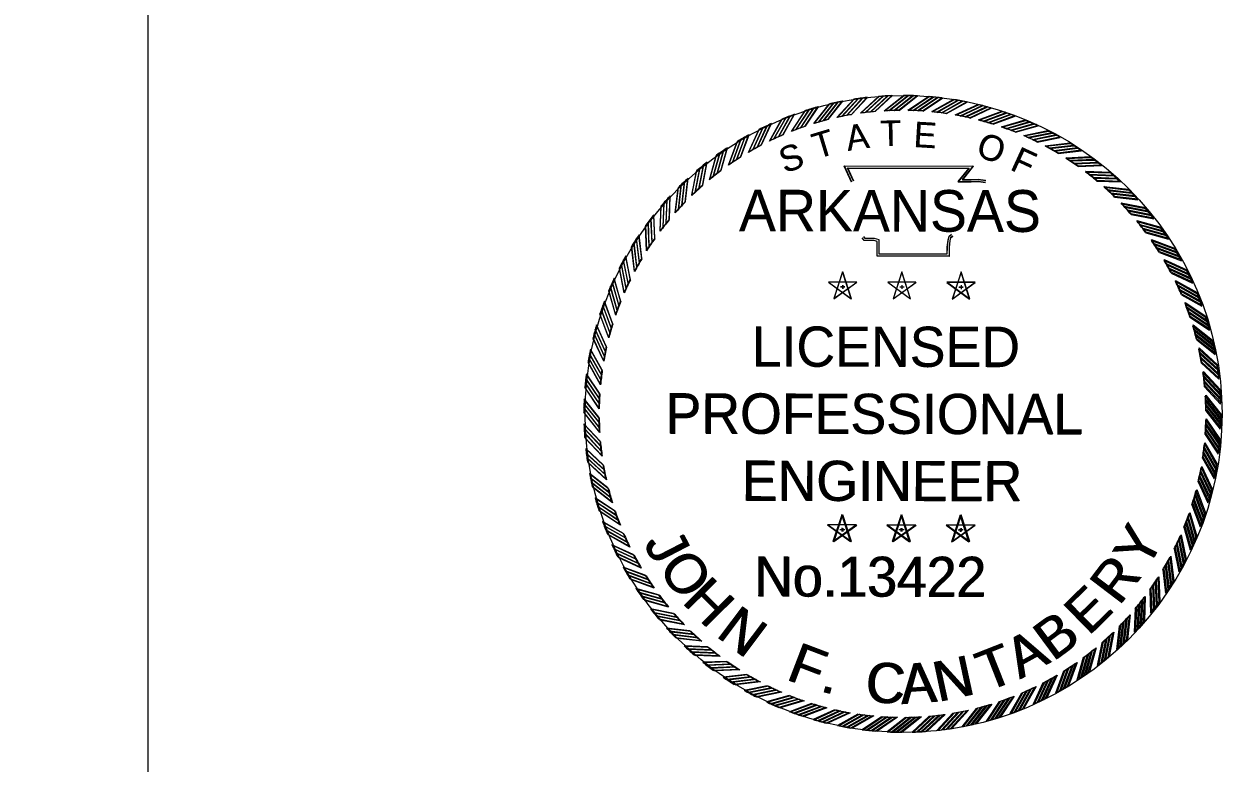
# Model space of a CAD drawing. Extents: x 0 to 19, y -0.6 to 11.2.
# Drawn here: x 16.766 to 19.023, y 7.658 to 9.05 of the extents above; entities that cross this region are included whole.
import ezdxf

# ---------------------------------------------------------------- set-up
doc = ezdxf.new("R2010")
doc.units = 0
for name, color, linetype in [('Default', 7, 'Continuous'), ('G-ANNO-SYMB', 7, 'Continuous'), ('G-ANNO-TEXT', 7, 'Continuous'), ('G-Border-Paper', 7, 'Continuous'), ('G-No Plot-Stamp-1', 7, 'Continuous')]:
    doc.layers.add(name, color=color, linetype=linetype)

# ---------------------------------------------------------------- blocks, each defined once
blk = doc.blocks.new('STAR')
at = {"layer": 'Default'}
for p, q in [((-0.0001, 0.0615), (-0.0366, -0.0504)), ((0.0362, -0.0503), (0, 0.0617)), ((0.0587, 0.0188), (-0.059, 0.0189)), ((-0.0589, 0.0188), (0.0363, -0.0505)), ((-0.0365, -0.0503), (0.0589, 0.0188)), ((-0.0085, 0), (0.009, 0)), ((0, 0.0063), (0, -0.0085))]:
    blk.add_line(p, q, dxfattribs=at)
blk = doc.blocks.new('RP')
at = {"layer": 'Default'}
for p, q in [((-0.0781, 1.2656), (0.003, 1.33)), ((-0.058, 1.2667), (0.0216, 1.3299)), ((-0.0375, 1.2674), (0.0405, 1.3294)), ((-0.0176, 1.2679), (0.059, 1.3287))]:
    blk.add_line(p, q, dxfattribs=at)
for radius, start, end in [(1.33, 87.4562, 89.8699), (1.268, 90.7933, 93.5307)]:
    blk.add_arc((0, 0), radius, start, end, dxfattribs=at)

msp = doc.modelspace()

# ---------------------------------------------------------------- linework, layer by layer
at = {"layer": 'G-ANNO-SYMB'}
for points in [[(18.3256, 8.7521), (18.3116, 8.7824), (18.5542, 8.7826), (18.5339, 8.7571), (18.5504, 8.7573), (18.5641, 8.7575), (18.5779, 8.756)], [(18.3261, 8.7522), (18.3121, 8.7827), (18.5547, 8.782), (18.5344, 8.7566), (18.5509, 8.7567), (18.5646, 8.7569), (18.5784, 8.7553)], [(18.3291, 8.7537), (18.3176, 8.7786), (18.5462, 8.7787), (18.5258, 8.7532), (18.5504, 8.7535), (18.564, 8.7537), (18.5775, 8.7522)], [(18.3295, 8.7538), (18.3181, 8.7788), (18.5468, 8.7781), (18.5263, 8.7526), (18.5509, 8.7529), (18.5644, 8.753), (18.5779, 8.7515)], [(18.5159, 8.6504), (18.5118, 8.647), (18.5104, 8.642), (18.509, 8.6294), (18.509, 8.6127), (18.3736, 8.6127), (18.3736, 8.6353), (18.3736, 8.6403), (18.3681, 8.642), (18.3489, 8.642), (18.3454, 8.6472)], [(18.5161, 8.6499), (18.5119, 8.6466), (18.5105, 8.6415), (18.5091, 8.629), (18.509, 8.6122), (18.3736, 8.6127), (18.3737, 8.6353), (18.3737, 8.6403), (18.3682, 8.642), (18.349, 8.6421), (18.3456, 8.6473)], [(18.5135, 8.6534), (18.5084, 8.6492), (18.5066, 8.6427), (18.5052, 8.6296), (18.5052, 8.6165), (18.3775, 8.6165), (18.3775, 8.6353), (18.3775, 8.6432), (18.3687, 8.6459), (18.3509, 8.6459), (18.3487, 8.6493)], [(18.5136, 8.6529), (18.5085, 8.6488), (18.5067, 8.6423), (18.5053, 8.6292), (18.5052, 8.6161), (18.3775, 8.6165), (18.3775, 8.6353), (18.3776, 8.6432), (18.3688, 8.6459), (18.3511, 8.6459), (18.3488, 8.6494)]]:
    msp.add_lwpolyline(points, dxfattribs=at)
at = {"layer": 'G-Border-Paper'}
msp.add_lwpolyline([(17, 11), (0, 11), (0, 0), (17, 0)], close=True, dxfattribs=at)
at = {"layer": 'G-No Plot-Stamp-1'}
msp.add_circle((18.4233, 8.3154), 0.6, dxfattribs=at)

# ---------------------------------------------------------------- block references
at = {"layer": 'G-ANNO-SYMB'}
for name, p, xscale, yscale, rotation in [('RP', (18.4219, 8.3156), 0.45103579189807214, 0.4510357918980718, 4.500000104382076), ('RP', (18.4209, 8.3154), 0.451035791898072, 0.45103579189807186, 4.304199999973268), ('RP', (18.4219, 8.3156), 0.451035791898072, 0.45103579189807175, 1.0438208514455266e-07), ('RP', (18.4209, 8.3154), 0.45103579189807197, 0.4510357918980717, -0.19580000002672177), ('RP', (18.4219, 8.3156), 0.451035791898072, 0.4510357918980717, -4.499999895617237), ('RP', (18.4209, 8.3154), 0.451035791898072, 0.45103579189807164, -4.695800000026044), ('RP', (18.4219, 8.3156), 0.4510357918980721, 0.4510357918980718, 18.00000010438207), ('RP', (18.4209, 8.3154), 0.45103579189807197, 0.4510357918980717, 17.804199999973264), ('RP', (18.4219, 8.3156), 0.45103579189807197, 0.45103579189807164, 13.500000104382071), ('RP', (18.4209, 8.3154), 0.45103579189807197, 0.45103579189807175, 13.304199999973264), ('RP', (18.4219, 8.3156), 0.45103579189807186, 0.4510357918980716, 9.000000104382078), ('RP', (18.4209, 8.3154), 0.4510357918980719, 0.45103579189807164, 8.804199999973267), ('RP', (18.4219, 8.3156), 0.4510357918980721, 0.45103579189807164, -8.999999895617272), ('RP', (18.4209, 8.3154), 0.45103579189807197, 0.45103579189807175, -9.195800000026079), ('RP', (18.4219, 8.3156), 0.45103579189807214, 0.45103579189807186, -13.499999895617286), ('RP', (18.4209, 8.3154), 0.4510357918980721, 0.4510357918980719, -13.695800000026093), ('RP', (18.4219, 8.3156), 0.45103579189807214, 0.4510357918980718, -17.99999989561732), ('RP', (18.4209, 8.3154), 0.4510357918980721, 0.4510357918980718, -18.19580000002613), ('RP', (18.4219, 8.3156), 0.45103579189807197, 0.45103579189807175, 22.500000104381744), ('RP', (18.4209, 8.3154), 0.451035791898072, 0.4510357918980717, 22.304199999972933), ('RP', (18.4219, 8.3156), 0.451035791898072, 0.45103579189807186, -22.499999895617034), ('RP', (18.4209, 8.3154), 0.45103579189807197, 0.4510357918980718, -22.695800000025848), ('RP', (18.4219, 8.3156), 0.451035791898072, 0.45103579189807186, 27.000000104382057), ('RP', (18.4209, 8.3154), 0.45103579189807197, 0.4510357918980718, 26.80419999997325), ('RP', (18.4219, 8.3156), 0.4510357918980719, 0.45103579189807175, -26.99999989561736), ('RP', (18.4209, 8.3154), 0.45103579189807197, 0.45103579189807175, -27.19580000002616), ('RP', (18.4219, 8.3156), 0.45103579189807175, 0.45103579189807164, 31.500000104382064), ('RP', (18.4209, 8.3154), 0.4510357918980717, 0.4510357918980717, 31.30419999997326), ('RP', (18.4219, 8.3156), 0.45103579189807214, 0.45103579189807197, -31.49999989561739), ('RP', (18.4209, 8.3154), 0.4510357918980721, 0.45103579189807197, -31.695800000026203), ('RP', (18.4219, 8.3156), 0.4510357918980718, 0.45103579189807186, 36.00000010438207), ('RP', (18.4209, 8.3154), 0.4510357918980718, 0.45103579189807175, 35.80419999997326), ('RP', (18.4219, 8.3156), 0.4510357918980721, 0.4510357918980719, -35.999999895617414), ('RP', (18.4209, 8.3154), 0.451035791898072, 0.45103579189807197, -36.195800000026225), ('RP', (18.4219, 8.3156), 0.4510357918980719, 0.45103579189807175, 40.50000010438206), ('RP', (18.4209, 8.3154), 0.45103579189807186, 0.45103579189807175, 40.30419999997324), ('RP', (18.4219, 8.3156), 0.45103579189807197, 0.451035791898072, -40.49999989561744), ('RP', (18.4209, 8.3154), 0.45103579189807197, 0.45103579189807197, -40.69580000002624), ('RP', (18.4219, 8.3156), 0.45103579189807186, 0.451035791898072, 45.00000010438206), ('RP', (18.4209, 8.3154), 0.45103579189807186, 0.4510357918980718, 44.80419999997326), ('RP', (18.4219, 8.3156), 0.45103579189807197, 0.45103579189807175, -44.99999989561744), ('RP', (18.4209, 8.3154), 0.4510357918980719, 0.45103579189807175, -45.19580000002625), ('RP', (18.4219, 8.3156), 0.45103579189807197, 0.451035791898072, 49.500000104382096), ('RP', (18.4209, 8.3154), 0.451035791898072, 0.451035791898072, 49.304199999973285), ('RP', (18.4219, 8.3156), 0.4510357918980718, 0.4510357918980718, -49.499999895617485), ('RP', (18.4209, 8.3154), 0.4510357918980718, 0.45103579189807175, -49.695800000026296), ('RP', (18.4219, 8.3156), 0.45103579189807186, 0.4510357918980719, 54.00000010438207), ('RP', (18.4209, 8.3154), 0.4510357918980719, 0.4510357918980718, 53.804199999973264), ('RP', (18.4219, 8.3156), 0.45103579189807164, 0.45103579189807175, -53.999999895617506), ('RP', (18.4209, 8.3154), 0.45103579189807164, 0.4510357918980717, -54.1958000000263), ('RP', (18.4209, 8.3154), 0.45103579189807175, 0.4510357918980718, 58.304199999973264), ('RP', (18.4219, 8.3156), 0.4510357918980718, 0.4510357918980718, 58.50000010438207), ('RP', (18.4219, 8.3156), 0.4510357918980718, 0.4510357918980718, -58.49999989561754), ('RP', (18.4209, 8.3154), 0.45103579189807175, 0.4510357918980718, -58.69580000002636), ('RP', (18.4209, 8.3154), 0.4510357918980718, 0.4510357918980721, 62.804199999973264), ('RP', (18.4219, 8.3156), 0.4510357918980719, 0.451035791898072, 63.000000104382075), ('RP', (18.4219, 8.3156), 0.45103579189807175, 0.45103579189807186, -62.999999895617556), ('RP', (18.4209, 8.3154), 0.4510357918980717, 0.4510357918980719, -63.19580000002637), ('STAR', (18.3085, 8.5553), 0.45103579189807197, 0.4510357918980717, -0.19580000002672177), ('STAR', (18.3087, 8.5551), 0.451035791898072, 0.45103579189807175, 1.0438208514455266e-07), ('STAR', (18.4201, 8.5549), 0.45103579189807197, 0.4510357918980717, -0.19580000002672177), ('STAR', (18.4203, 8.5551), 0.451035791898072, 0.45103579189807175, 1.0438208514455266e-07), ('STAR', (18.5316, 8.5545), 0.45103579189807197, 0.4510357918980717, -0.19580000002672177), ('STAR', (18.5318, 8.5551), 0.451035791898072, 0.45103579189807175, 1.0438208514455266e-07), ('RP', (18.4219, 8.3156), 0.45103579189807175, 0.45103579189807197, -67.49999989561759), ('RP', (18.4209, 8.3154), 0.4510357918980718, 0.4510357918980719, 67.30419999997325), ('RP', (18.4219, 8.3156), 0.4510357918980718, 0.45103579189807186, 67.50000010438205), ('RP', (18.4209, 8.3154), 0.4510357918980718, 0.45103579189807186, -67.69580000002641), ('RP', (18.4209, 8.3154), 0.45103579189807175, 0.45103579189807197, -72.19580000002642), ('RP', (18.4219, 8.3156), 0.4510357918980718, 0.45103579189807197, -71.99999989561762), ('RP', (18.4209, 8.3154), 0.45103579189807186, 0.451035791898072, 71.80419999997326), ('RP', (18.4219, 8.3156), 0.4510357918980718, 0.4510357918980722, 72.00000010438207), ('RP', (18.4209, 8.3154), 0.4510357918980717, 0.4510357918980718, -76.69580000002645), ('RP', (18.4219, 8.3156), 0.45103579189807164, 0.4510357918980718, -76.49999989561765), ('RP', (18.4209, 8.3154), 0.4510357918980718, 0.4510357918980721, 76.30419999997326), ('RP', (18.4219, 8.3156), 0.4510357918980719, 0.451035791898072, 76.50000010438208), ('RP', (18.4209, 8.3154), 0.45103579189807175, 0.45103579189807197, -81.19580000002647), ('RP', (18.4219, 8.3156), 0.4510357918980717, 0.4510357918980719, -80.99999989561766), ('RP', (18.4209, 8.3154), 0.4510357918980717, 0.45103579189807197, 80.80419999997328), ('RP', (18.4219, 8.3156), 0.4510357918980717, 0.451035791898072, 81.0000001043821), ('RP', (18.4219, 8.3156), 0.45103579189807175, 0.4510357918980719, -85.49999989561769), ('RP', (18.4209, 8.3154), 0.4510357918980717, 0.4510357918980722, 85.30419999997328), ('RP', (18.4219, 8.3156), 0.45103579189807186, 0.451035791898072, 85.50000010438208), ('RP', (18.4209, 8.3154), 0.4510357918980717, 0.4510357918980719, -85.69580000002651), ('RP', (18.4209, 8.3154), 0.45103579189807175, 0.451035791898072, 89.80419999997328), ('RP', (18.4219, 8.3156), 0.45103579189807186, 0.45103579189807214, 90.0000001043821), ('RP', (18.4209, 8.3154), 0.4510357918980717, 0.451035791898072, -90.19580000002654), ('RP', (18.4219, 8.3156), 0.45103579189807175, 0.45103579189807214, -89.99999989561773), ('RP', (18.4209, 8.3154), 0.45103579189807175, 0.4510357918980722, 94.30419999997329), ('RP', (18.4219, 8.3156), 0.45103579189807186, 0.4510357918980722, 94.5000001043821), ('RP', (18.4209, 8.3154), 0.4510357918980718, 0.45103579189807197, -94.69580000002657), ('RP', (18.4219, 8.3156), 0.45103579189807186, 0.4510357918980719, -94.49999989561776), ('RP', (18.4219, 8.3156), 0.4510357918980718, 0.45103579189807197, -98.99999989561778), ('RP', (18.4209, 8.3154), 0.45103579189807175, 0.45103579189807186, 98.8041999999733), ('RP', (18.4219, 8.3156), 0.4510357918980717, 0.4510357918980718, 99.0000001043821), ('RP', (18.4209, 8.3154), 0.45103579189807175, 0.45103579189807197, -99.19580000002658), ('RP', (18.4219, 8.3156), 0.4510357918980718, 0.45103579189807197, -103.49999989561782), ('RP', (18.4209, 8.3154), 0.4510357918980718, 0.4510357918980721, 103.30419999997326), ('RP', (18.4219, 8.3156), 0.45103579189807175, 0.451035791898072, 103.50000010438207), ('RP', (18.4209, 8.3154), 0.4510357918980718, 0.45103579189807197, -103.69580000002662), ('RP', (18.4209, 8.3154), 0.45103579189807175, 0.45103579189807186, -108.19580000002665), ('RP', (18.4219, 8.3156), 0.4510357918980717, 0.451035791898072, -107.99999989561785), ('RP', (18.4209, 8.3154), 0.45103579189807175, 0.4510357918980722, 107.80419999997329), ('RP', (18.4219, 8.3156), 0.45103579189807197, 0.45103579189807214, 108.0000001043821), ('STAR', (18.3069, 8.0978), 0.45103579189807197, 0.4510357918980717, -0.19580000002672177), ('STAR', (18.3087, 8.0976), 0.451035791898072, 0.45103579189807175, 1.0438208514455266e-07), ('STAR', (18.4185, 8.0974), 0.45103579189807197, 0.4510357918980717, -0.19580000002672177), ('STAR', (18.4203, 8.0976), 0.451035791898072, 0.45103579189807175, 1.0438208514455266e-07), ('STAR', (18.5318, 8.0976), 0.451035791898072, 0.45103579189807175, 1.0438208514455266e-07), ('RP', (18.4209, 8.3154), 0.4510357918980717, 0.4510357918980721, -112.69580000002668), ('RP', (18.4219, 8.3156), 0.45103579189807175, 0.45103579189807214, -112.49999989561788), ('RP', (18.4209, 8.3154), 0.45103579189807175, 0.45103579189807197, 112.30419999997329), ('RP', (18.4219, 8.3156), 0.4510357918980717, 0.45103579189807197, 112.5000001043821), ('STAR', (18.5301, 8.097), 0.45103579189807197, 0.4510357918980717, -0.19580000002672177), ('RP', (18.4209, 8.3154), 0.4510357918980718, 0.45103579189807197, 116.80419999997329), ('RP', (18.4209, 8.3154), 0.4510357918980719, 0.451035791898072, -117.19580000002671), ('RP', (18.4219, 8.3156), 0.451035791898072, 0.4510357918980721, -116.9999998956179), ('RP', (18.4219, 8.3156), 0.4510357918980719, 0.45103579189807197, 117.0000001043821), ('RP', (18.4209, 8.3154), 0.45103579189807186, 0.45103579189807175, 121.30419999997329), ('RP', (18.4219, 8.3156), 0.45103579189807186, 0.45103579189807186, 121.5000001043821), ('RP', (18.4209, 8.3154), 0.4510357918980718, 0.4510357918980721, -121.69580000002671), ('RP', (18.4219, 8.3156), 0.4510357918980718, 0.4510357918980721, -121.4999998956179), ('RP', (18.4209, 8.3154), 0.45103579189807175, 0.45103579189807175, 125.80419999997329), ('RP', (18.4219, 8.3156), 0.4510357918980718, 0.4510357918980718, 126.00000010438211), ('RP', (18.4209, 8.3154), 0.4510357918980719, 0.45103579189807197, -126.19580000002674), ('RP', (18.4219, 8.3156), 0.45103579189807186, 0.45103579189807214, -125.99999989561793), ('RP', (18.4209, 8.3154), 0.45103579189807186, 0.4510357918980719, -130.6958000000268), ('RP', (18.4219, 8.3156), 0.45103579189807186, 0.4510357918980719, -130.49999989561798), ('RP', (18.4209, 8.3154), 0.4510357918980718, 0.4510357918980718, 130.3041999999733), ('RP', (18.4219, 8.3156), 0.4510357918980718, 0.45103579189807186, 130.50000010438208), ('RP', (18.4209, 8.3154), 0.45103579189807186, 0.4510357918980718, 134.80419999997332), ('RP', (18.4219, 8.3156), 0.45103579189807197, 0.4510357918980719, 135.00000010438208), ('RP', (18.4209, 8.3154), 0.45103579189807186, 0.4510357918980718, -135.19580000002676), ('RP', (18.4219, 8.3156), 0.45103579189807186, 0.451035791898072, -134.99999989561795), ('RP', (18.4209, 8.3154), 0.4510357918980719, 0.45103579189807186, 139.30419999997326), ('RP', (18.4209, 8.3154), 0.4510357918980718, 0.45103579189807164, -139.69580000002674), ('RP', (18.4219, 8.3156), 0.4510357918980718, 0.45103579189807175, -139.49999989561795), ('RP', (18.4219, 8.3156), 0.4510357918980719, 0.45103579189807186, 139.50000010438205), ('RP', (18.4209, 8.3154), 0.451035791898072, 0.45103579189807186, 143.8041999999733), ('RP', (18.4219, 8.3156), 0.4510357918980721, 0.4510357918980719, 144.00000010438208), ('RP', (18.4209, 8.3154), 0.4510357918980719, 0.4510357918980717, -144.19580000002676), ('RP', (18.4219, 8.3156), 0.45103579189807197, 0.45103579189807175, -143.99999989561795), ('RP', (18.4209, 8.3154), 0.4510357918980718, 0.45103579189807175, 148.3041999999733), ('RP', (18.4219, 8.3156), 0.4510357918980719, 0.4510357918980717, 148.50000010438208), ('RP', (18.4209, 8.3154), 0.45103579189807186, 0.45103579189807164, -148.69580000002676), ('RP', (18.4219, 8.3156), 0.45103579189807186, 0.45103579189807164, -148.49999989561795), ('RP', (18.4209, 8.3154), 0.4510357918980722, 0.4510357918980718, 152.8041999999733), ('RP', (18.4219, 8.3156), 0.4510357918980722, 0.45103579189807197, 153.00000010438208), ('RP', (18.4209, 8.3154), 0.45103579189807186, 0.45103579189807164, -153.1958000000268), ('RP', (18.4219, 8.3156), 0.4510357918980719, 0.4510357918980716, -152.99999989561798), ('RP', (18.4209, 8.3154), 0.45103579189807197, 0.4510357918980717, 157.3041999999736), ('RP', (18.4219, 8.3156), 0.4510357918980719, 0.4510357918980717, 157.50000010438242), ('RP', (18.4209, 8.3154), 0.45103579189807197, 0.4510357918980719, -157.6958000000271), ('RP', (18.4219, 8.3156), 0.45103579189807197, 0.4510357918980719, -157.4999998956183), ('RP', (18.4209, 8.3154), 0.4510357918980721, 0.4510357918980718, 161.8041999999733), ('RP', (18.4219, 8.3156), 0.45103579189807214, 0.4510357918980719, 162.00000010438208), ('RP', (18.4209, 8.3154), 0.4510357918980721, 0.4510357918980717, 166.3041999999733), ('RP', (18.4219, 8.3156), 0.4510357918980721, 0.4510357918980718, 166.50000010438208), ('RP', (18.4209, 8.3154), 0.45103579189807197, 0.45103579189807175, -166.69580000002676), ('RP', (18.4219, 8.3156), 0.45103579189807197, 0.45103579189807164, -166.49999989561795), ('RP', (18.4209, 8.3154), 0.45103579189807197, 0.4510357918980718, -162.19580000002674), ('RP', (18.4219, 8.3156), 0.4510357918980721, 0.45103579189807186, -161.99999989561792), ('RP', (18.4209, 8.3154), 0.45103579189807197, 0.4510357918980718, 170.8041999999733), ('RP', (18.4219, 8.3156), 0.45103579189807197, 0.4510357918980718, 171.00000010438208), ('RP', (18.4209, 8.3154), 0.451035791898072, 0.45103579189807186, 175.3041999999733), ('RP', (18.4219, 8.3156), 0.45103579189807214, 0.45103579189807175, 175.50000010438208), ('RP', (18.4209, 8.3154), 0.451035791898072, 0.45103579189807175, 179.8041999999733), ('RP', (18.4219, 8.3156), 0.45103579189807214, 0.45103579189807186, -179.99999989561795), ('RP', (18.4209, 8.3154), 0.4510357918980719, 0.45103579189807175, -175.69580000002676), ('RP', (18.4219, 8.3156), 0.45103579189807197, 0.45103579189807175, -175.49999989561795), ('RP', (18.4209, 8.3154), 0.4510357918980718, 0.45103579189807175, -171.19580000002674), ('RP', (18.4219, 8.3156), 0.45103579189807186, 0.4510357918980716, -170.99999989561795)]:
    msp.add_blockref(name, p, dxfattribs=dict(at, xscale=xscale, yscale=yscale, rotation=rotation))

# ---------------------------------------------------------------- texts
at = {"layer": 'G-ANNO-TEXT'}
for s, height, rotation, p in [('T', 0.0479, 16.9015, (18.2601, 8.7953)), ('T', 0.0479, 16.7057, (18.2607, 8.7957)), ('A', 0.0479, 8.6788, (18.3182, 8.8105)), ('A', 0.0479, 8.483, (18.3189, 8.8107)), ('T', 0.0479, 1.4789, (18.38, 8.82)), ('T', 0.0479, 1.2831, (18.3807, 8.82)), ('E', 0.0479, 356.672, (18.4412, 8.8185)), ('E', 0.0479, 356.4762, (18.4419, 8.8183)), ('O', 0.0479, 341.2218, (18.5574, 8.8021)), ('O', 0.0479, 341.026, (18.5581, 8.8015)), ('S', 0.0479, 19.7726, (18.1992, 8.768)), ('S', 0.0479, 19.5768, (18.1998, 8.7686)), ('F', 0.0479, 335.3628, (18.6219, 8.7769)), ('F', 0.0479, 335.167, (18.6225, 8.7761)), ('ARKANSAS', 0.0781, 0, (18.1132, 8.6591)), ('ARKANSAS', 0.0781, 359.8042, (18.1134, 8.66)), ('LICENSED', 0.07561, 359.8042, (18.1368, 8.405)), ('LICENSED', 0.07561, 0, (18.1375, 8.4042)), ('PROFESSIONAL', 0.075612, 359.8042, (17.9743, 8.2791)), ('PROFESSIONAL', 0.075612, 0, (17.9755, 8.2777)), ('ENGINEER', 0.07561, 359.8042, (18.1179, 8.1522)), ('ENGINEER', 0.07561, 0, (18.1195, 8.1513)), ('Y', 0.0756, 62.5392, (18.8819, 8.0186)), ('Y', 0.0756, 62.735, (18.8839, 8.0204)), ('J', 0.0756, 297.2813, (17.9322, 8.0724)), ('J', 0.0756, 297.4771, (17.934, 8.0709)), ('O', 0.0756, 304.1899, (17.959, 8.026)), ('O', 0.0756, 304.3857, (17.961, 8.0246)), ('No.13422', 0.07531, 359.8042, (18.1412, 7.9718)), ('No.13422', 0.07531, 0, (18.1434, 7.9711)), ('R', 0.0756, 52.7437, (18.8291, 7.9521)), ('R', 0.0756, 52.9395, (18.8313, 7.9536)), ('H', 0.0756, 314.7447, (18.0036, 7.9609)), ('H', 0.0756, 314.9405, (18.0058, 7.9596)), ('E', 0.0756, 44.306, (18.7715, 7.8958)), ('E', 0.0756, 44.5018, (18.7739, 7.8971)), ('N', 0.0756, 322.9417, (18.0674, 7.8976)), ('N', 0.0756, 323.1375, (18.0698, 7.8966)), ('B', 0.0756, 36.505, (18.7047, 7.8477)), ('B', 0.0756, 36.7008, (18.7074, 7.8488)), ('A', 0.0756, 28.8562, (18.6419, 7.8147)), ('A', 0.0756, 29.052, (18.6447, 7.8156)), ('F', 0.0756, 339.0288, (18.1994, 7.8157)), ('F', 0.0756, 339.2246, (18.2021, 7.8152)), ('T', 0.0756, 21.4329, (18.5791, 7.791)), ('T', 0.0756, 21.6287, (18.5819, 7.7917)), ('N', 0.0756, 12.0703, (18.4879, 7.7722)), ('N', 0.0756, 12.2661, (18.4907, 7.7726)), ('C', 0.0756, 356.1028, (18.3494, 7.7733)), ('C', 0.0756, 356.2986, (18.3523, 7.7732)), ('A', 0.0756, 3.9092, (18.4187, 7.7683)), ('A', 0.0756, 4.105, (18.4216, 7.7685)), ('.', 0.0756, 344.7037, (18.2639, 7.7934)), ('.', 0.0756, 344.8995, (18.2667, 7.793))]:
    msp.add_text(s, height=height, rotation=rotation, dxfattribs=at).set_placement(p)

doc.saveas('drawing.dxf')
